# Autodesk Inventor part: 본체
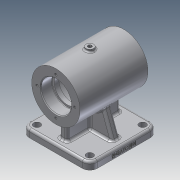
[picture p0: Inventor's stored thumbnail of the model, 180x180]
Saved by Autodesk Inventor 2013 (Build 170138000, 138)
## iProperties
Created: 2019-06
Part Number: 본체
Material: 알루미늄 6061
Document SubType Name: Modeling
Designer: user
Density: 2.71 g/cm^3
Mass: 612.592 g
Surface Area: 621.749 cm^2
Volume: 226.049 cm^3
Author: user
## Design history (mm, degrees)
sketch "스케치1"
  geometry: C1 r 32 at (0, 0); 1 further point
  constraints: 1 centre point, 1 coincident
  dimensions: "d0" = 64 diameter of C1
extrude "돌출1" new body sketch "스케치1" stored distance "d1" = 90; taper "d2" = 0 deg
sketch "스케치2"
  geometry: L1 (32, 45)-(-32, 45) reference; L2 (-32, -45)-(32, -45) reference; L3 (0, 45)-(0, -45); L4 (20, 45)-(20, 30); L5 (20, 30)-(17, 30); L6 (17, 30)-(17, 24); L7 (17, 24)-(25, 24); L8 (25, 24)-(25, -24); L9 (25, -24)-(17, -24); L10 (17, -24)-(17, -30); L11 (17, -30)-(20, -30); L12 (20, -30)-(20, -45); 1 further point
  constraints: 20 end point, 5 perpendicular, 4 parallel, 2 midpoint, 2 point on line
  dimensions: "d3" = 15 distance of L4.start L4.end; "d5" = 15 distance of L11.end L12.end; "d6" = 6 distance of L5.end L6.end; "d7" = 6 distance of L9.end L10.end; "d8" = 40 diameter of L4 L3; "d9" = 40 diameter of L12 L3; "d10" = 50 diameter of L8 L3; "d11" = 34 diameter of L6 L3; "d12" = 34 diameter of L10 L3
revolve "회전1" sketch "스케치2" stored, may be unused: angle "d13" = 90 deg
chamfer "모따기1" distance "d14" = 1; stored, may be unused: second distance "d15" = 2, angle "d16" = 45 deg
fillet "모깎기1" dims "d17" = 3
fillet "모깎기2" dims "d18" = 0.6
sketch "스케치3"
  geometry: L1 (0, 0)-(0, 25); C1 r 21 at (0, 0) reference; 1 further point
  constraints: 2 end point, 1 coincident, 1 vertical
  dimensions: "d19" = 25 distance of L1.start L1.end
hole "구멍1" sketch "스케치3" at (0, 25) diameter "d20" = 3.242; stored, may be unused: countersink angle "d24" = 90 deg, drill point angle "d26" = 118 deg; dims "d21" = 7, "d22" = 4, "d23" = 2, "d25" = 9
node "작업 평면1"
sketch "스케치4"
  geometry: L1 (45, -45)-(-45, -45); L2 (-45, -45)-(-45, 45); L3 (-45, 45)-(45, 45); L4 (45, 45)-(45, -45); L5 (45, -45)-(-45, 45); L6 (-45, -45)-(45, 45); 1 further point
  constraints: 12 end point, 2 midpoint, 2 parallel, 1 horizontal, 1 perpendicular
  dimensions: "d31" = 90 distance of L2.end L3.end; "d32" = 90 distance of L1.end L2.end
extrude "돌출2" join sketch "스케치4" distance "d33" = 10; taper "d34" = 0 deg
fillet "모깎기3" dims "d35" = 10
sketch "스케치5"
  geometry: A1 r 10 centre (-35, -35) between (-45, -35) and (-35, -45) reference; A2 r 10 centre (35, -35) between (35, -45) and (45, -35) reference; A3 r 10 centre (35, 35) between (45, 35) and (35, 45) reference; A4 r 10 centre (-35, 35) between (-35, 45) and (-45, 35) reference; 5 further points
  constraints: 4 coincident
hole "구멍2" sketch "스케치5" at (-35, 35), (35, 35), (35, -35), (-35, -35) diameter "d36" = 9; stored, may be unused: countersink angle "d40" = 90 deg, drill point angle "d42" = 118 deg; dims "d37" = 7, "d38" = 4, "d39" = 2, "d41" = 9
sketch "스케치6"
  geometry: L1 (5, -35)-(-5, -35); L2 (-5, -35)-(-5, 35); L3 (-5, 35)-(5, 35); L4 (5, 35)-(5, -35); L5 (5, -35)-(-5, 35); L6 (-5, -35)-(5, 35); 1 further point
  constraints: 12 end point, 2 midpoint, 2 parallel, 1 horizontal, 1 perpendicular
  dimensions: "d43" = 10 distance of L2.end L3.end; "d44" = 70 distance of L1.end L2.end
extrude "돌출3" join sketch "스케치6" stored distance "d45" = 10; taper "d46" = 0 deg
sketch "스케치7"
  geometry: L1 (35, -55)-(-35, -55) reference; L2 (23.058, -22.189)-(35, -55); L3 (45, -55)-(45, -65) reference; 2 further points
  constraints: 2 end point, 1 point on line, 2 other
  dimensions: "d47" = 110 deg angle of L1 L2; "d48" = 10 distance of L3.start L2.end
feature "리브1" sketch "스케치7" dims "d49" = 1, "d50" = 10, "d51" = 0, "d52" = 0, "d53" = 1, "d54" = 1
node "작업 평면2"
sketch "스케치8"
  geometry: C1 r 5 at (0, 0); 1 further point
  constraints: 1 centre point, 1 coincident
  dimensions: "d56" = 10 diameter of C1
extrude "돌출4" join sketch "스케치8" stored distance "d57" = 10; taper "d58" = 0 deg
sketch "스케치9"
  geometry: C1 r 5 at (0, 0) reference; 1 further point
  constraints: 1 coincident
hole "구멍3" sketch "스케치9" at (0, 0) diameter "d59" = 4.917; stored, may be unused: countersink angle "d63" = 90 deg, drill point angle "d65" = 118 deg; dims "d60" = 20, "d61" = 4, "d62" = 2, "d64" = 9
fillet "모깎기4" dims "d66" = 2
sketch "스케치11"
  geometry: L1 (40, -40)-(-40, -40); L2 (-40, -40)-(-40, 40); L3 (-40, 40)-(40, 40); L4 (40, 40)-(40, -40); C1 r 4.5 at (-35, 35) reference; C2 r 4.5 at (35, -35) reference; C3 r 4.5 at (-35, -35) reference; C4 r 4.5 at (35, 35) reference; 3 further points
  constraints: 8 end point, 2 midpoint, 2 parallel, 1 horizontal, 1 horizontal alignment, 1 perpendicular, 1 vertical alignment
  dimensions: "d73" = 80 distance of L2.end L3.end; "d74" = 80 distance of L1.end L2.end
extrude "돌출5" cut sketch "스케치11" distance "d76" = 5; taper "d77" = 0 deg
sketch "스케치12"
  geometry: C1 r 4.5 at (35, 35) reference; C2 r 4.5 at (-35, -35) reference; C3 r 4.5 at (35, -35) reference; C4 r 4.5 at (-35, 35) reference; C5 r 10 at (35, -35); C6 r 10 at (-35, -35); C7 r 10 at (-35, 35); C8 r 10 at (35, 35); 1 further point
  constraints: 4 centre point, 4 coincident
  dimensions: "d78" = 20 diameter of C5; "d79" = 20 diameter of C6; "d80" = 20 diameter of C7; "d81" = 20 diameter of C8
extrude "돌출6" join sketch "스케치12" distance "d82" = 5; taper "d83" = 0 deg
fillet "모깎기5" dims "d84" = 3
fillet "모깎기6" dims "d85" = 3
fillet "모깎기7" dims "d86" = 3
fillet "모깎기8" dims "d87" = 3
fillet "모깎기9" dims "d88" = 3
sketch "스케치13"
  geometry: L1 (0, 0)-(-10, 0) reference; 2 further points
  constraints: 1 other
  dimensions: "d89" = 4 vertical distance of point (35, 4) L1.end; "d90" = 45 horizontal distance of point (35, 4) L1.end
feature "엠보싱1" sketch "스케치13" dims "d91" = 0.5, "d92" = 0
node "솔리드1"
pattern_circular "원형 패턴1" dims angle "d28" = 360 deg
mirror "대칭1"
mirror "대칭2"
other parameters: "d30" = -65
